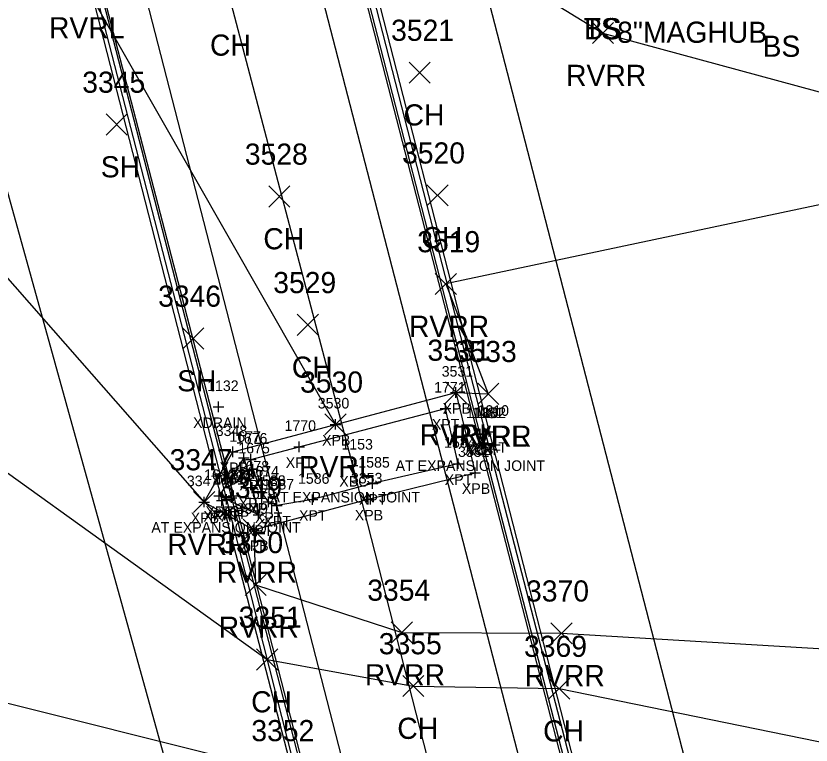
# Model space of a CAD drawing. Extents: x 1601151 to 1602912, y 499508 to 501770.
# Drawn here: x 1601542.5 to 1601617.7, y 500689.8 to 500758.7 of the extents above; entities that cross this region are included whole.
import ezdxf

# ---------------------------------------------------------------- set-up
doc = ezdxf.new("R2010")
doc.units = 0
for name, color, linetype in [('B_A', 7, 'Continuous'), ('B_C', 7, 'Continuous'), ('B_I', 7, 'Continuous'), ('B_TIC', 7, 'Continuous'), ('BB', 7, 'Continuous'), ('BDC', 7, 'Continuous'), ('BELB', 7, 'Continuous'), ('BF', 7, 'Continuous'), ('BR', 7, 'Continuous'), ('BSUBM', 7, 'Continuous'), ('C_C', 7, 'Continuous'), ('L_A', 7, 'Continuous'), ('L_I', 7, 'Continuous'), ('L_TIC', 7, 'Continuous'), ('LAWE', 7, 'Continuous'), ('LDEFAULT', 7, 'Continuous'), ('UCO', 7, 'Continuous')]:
    doc.layers.add(name, color=color, linetype=linetype)

msp = doc.modelspace()

# ---------------------------------------------------------------- linework, layer by layer
at = {"layer": 'B_TIC'}
for p, q in [((1601584.118, 500723.141), (1601584.193, 500723.141)), ((1601561.667, 500721.782), (1601561.743, 500721.782)), ((1601583.121, 500721.638), (1601583.197, 500721.638)), ((1601583.121, 500721.638), (1601583.197, 500721.638)), ((1601572.734, 500720.13), (1601572.81, 500720.13)), ((1601586.177, 500719.227), (1601586.253, 500719.227)), ((1601586.411, 500719.217), (1601586.487, 500719.217)), ((1601586.942, 500719.228), (1601587.018, 500719.228)), ((1601587.263, 500719.439), (1601587.339, 500719.439)), ((1601563.046, 500717.527), (1601563.122, 500717.527)), ((1601569.309, 500718.01), (1601569.385, 500718.01)), ((1601564.078, 500716.979), (1601564.154, 500716.979)), ((1601564.078, 500716.979), (1601564.154, 500716.979)), ((1601564.721, 500716.813), (1601564.797, 500716.813)), ((1601574.358, 500716.245), (1601574.434, 500716.245)), ((1601584.343, 500716.412), (1601584.419, 500716.412)), ((1601584.343, 500716.412), (1601584.419, 500716.412)), ((1601564.921, 500715.885), (1601564.997, 500715.885)), ((1601585.942, 500715.555), (1601586.018, 500715.555)), ((1601585.942, 500715.555), (1601586.018, 500715.555)), ((1601576.238, 500714.54), (1601576.314, 500714.54)), ((1601564.858, 500714.17), (1601564.934, 500714.17)), ((1601565.787, 500713.69), (1601565.863, 500713.69)), ((1601561.729, 500713.371), (1601561.805, 500713.371)), ((1601561.729, 500713.371), (1601561.805, 500713.371)), ((1601561.989, 500712.939), (1601562.065, 500712.939)), ((1601562.425, 500713.041), (1601562.501, 500713.041)), ((1601562.905, 500713.198), (1601562.981, 500713.198)), ((1601563.093, 500713.388), (1601563.169, 500713.388)), ((1601570.565, 500713.011), (1601570.641, 500713.011)), ((1601575.824, 500713.046), (1601575.899, 500713.046)), ((1601560.317, 500712.787), (1601560.393, 500712.787)), ((1601560.317, 500712.787), (1601560.393, 500712.787)), ((1601566.398, 500712.812), (1601566.474, 500712.812)), ((1601567.193, 500712.47), (1601567.269, 500712.47)), ((1601565.462, 500711.587), (1601565.538, 500711.587)), ((1601565.007, 500710.164), (1601565.082, 500710.164))]:
    msp.add_line(p, q, dxfattribs=at)
for points in [[(1601584.114, 500722.641), (1601584.114, 500723.641)], [(1601583.614, 500723.141), (1601584.614, 500723.141)], [(1601561.664, 500721.282), (1601561.664, 500722.282)], [(1601583.118, 500721.138), (1601583.118, 500722.138)], [(1601583.118, 500721.138), (1601583.118, 500722.138)], [(1601561.164, 500721.782), (1601562.164, 500721.782)], [(1601582.618, 500721.638), (1601583.618, 500721.638)], [(1601582.618, 500721.638), (1601583.618, 500721.638)], [(1601572.731, 500719.63), (1601572.731, 500720.63)], [(1601572.231, 500720.13), (1601573.231, 500720.13)], [(1601586.174, 500718.727), (1601586.174, 500719.727)], [(1601586.408, 500718.717), (1601586.408, 500719.717)], [(1601586.939, 500718.728), (1601586.939, 500719.728)], [(1601587.26, 500718.939), (1601587.26, 500719.939)], [(1601585.674, 500719.227), (1601586.674, 500719.227)], [(1601585.908, 500719.217), (1601586.908, 500719.217)], [(1601586.439, 500719.228), (1601587.439, 500719.228)], [(1601586.76, 500719.439), (1601587.76, 500719.439)], [(1601569.306, 500717.51), (1601569.306, 500718.51)], [(1601562.543, 500717.527), (1601563.543, 500717.527)], [(1601563.043, 500717.027), (1601563.043, 500718.027)], [(1601564.075, 500716.479), (1601564.075, 500717.479)], [(1601564.075, 500716.479), (1601564.075, 500717.479)], [(1601568.806, 500718.01), (1601569.806, 500718.01)], [(1601563.575, 500716.979), (1601564.575, 500716.979)], [(1601563.575, 500716.979), (1601564.575, 500716.979)], [(1601564.218, 500716.813), (1601565.218, 500716.813)], [(1601564.718, 500716.313), (1601564.718, 500717.313)], [(1601574.355, 500715.745), (1601574.355, 500716.745)], [(1601584.34, 500715.912), (1601584.34, 500716.912)], [(1601584.34, 500715.912), (1601584.34, 500716.912)], [(1601564.918, 500715.385), (1601564.918, 500716.385)], [(1601573.855, 500716.245), (1601574.855, 500716.245)], [(1601583.84, 500716.412), (1601584.84, 500716.412)], [(1601583.84, 500716.412), (1601584.84, 500716.412)], [(1601585.939, 500715.055), (1601585.939, 500716.055)], [(1601585.939, 500715.055), (1601585.939, 500716.055)], [(1601564.418, 500715.885), (1601565.418, 500715.885)], [(1601585.439, 500715.555), (1601586.439, 500715.555)], [(1601585.439, 500715.555), (1601586.439, 500715.555)], [(1601564.855, 500713.67), (1601564.855, 500714.67)], [(1601575.735, 500714.54), (1601576.735, 500714.54)], [(1601576.235, 500714.04), (1601576.235, 500715.04)], [(1601561.726, 500712.871), (1601561.726, 500713.871)], [(1601561.726, 500712.871), (1601561.726, 500713.871)], [(1601562.902, 500712.698), (1601562.902, 500713.698)], [(1601563.09, 500712.888), (1601563.09, 500713.888)], [(1601564.355, 500714.17), (1601565.355, 500714.17)], [(1601565.284, 500713.69), (1601566.284, 500713.69)], [(1601565.784, 500713.19), (1601565.784, 500714.19)], [(1601560.314, 500712.287), (1601560.314, 500713.287)], [(1601560.314, 500712.287), (1601560.314, 500713.287)], [(1601561.226, 500713.371), (1601562.226, 500713.371)], [(1601561.226, 500713.371), (1601562.226, 500713.371)], [(1601561.486, 500712.939), (1601562.486, 500712.939)], [(1601561.922, 500713.041), (1601562.922, 500713.041)], [(1601561.986, 500712.439), (1601561.986, 500713.439)], [(1601562.402, 500713.198), (1601563.402, 500713.198)], [(1601562.422, 500712.541), (1601562.422, 500713.541)], [(1601562.59, 500713.388), (1601563.59, 500713.388)], [(1601566.395, 500712.312), (1601566.395, 500713.312)], [(1601567.19, 500711.97), (1601567.19, 500712.97)], [(1601570.062, 500713.011), (1601571.062, 500713.011)], [(1601570.562, 500712.511), (1601570.562, 500713.511)], [(1601575.32, 500713.046), (1601576.32, 500713.046)], [(1601575.82, 500712.546), (1601575.82, 500713.546)], [(1601559.814, 500712.787), (1601560.814, 500712.787)], [(1601559.814, 500712.787), (1601560.814, 500712.787)], [(1601565.895, 500712.812), (1601566.895, 500712.812)], [(1601566.69, 500712.47), (1601567.69, 500712.47)], [(1601564.959, 500711.587), (1601565.959, 500711.587)], [(1601565.459, 500711.087), (1601565.459, 500712.087)], [(1601565.004, 500709.664), (1601565.004, 500710.664)], [(1601564.503, 500710.164), (1601565.504, 500710.164)]]:
    msp.add_lwpolyline(points, dxfattribs=at)
at = {"layer": 'BB'}
for points in [[(1601612.43, 500602.27), (1601552.33, 500834.638)], [(1601596.605, 500598.195), (1601536.682, 500830.877)]]:
    msp.add_lwpolyline(points, dxfattribs=at)
at = {"layer": 'BDC'}
for points in [[(1601626.62, 500562.484), (1601618.762, 500592.927), (1601608.069, 500634.25), (1601598.914, 500669.817), (1601586.174, 500719.227), (1601573.535, 500768.43), (1601563.157, 500808.618), (1601554.18, 500843.361), (1601545.696, 500876.636)], [(1601627.365, 500562.647), (1601626.817, 500562.743), (1601626.575, 500563.06), (1601618.94, 500592.981), (1601608.354, 500634.47), (1601599.142, 500669.932), (1601586.408, 500719.217), (1601573.699, 500768.593), (1601563.408, 500808.684), (1601554.3, 500843.382), (1601545.843, 500876.671)], [(1601521.711, 500869.959), (1601522.401, 500870.191), (1601530.668, 500838.288), (1601539.742, 500803.087), (1601549.8, 500763.941), (1601562.902, 500713.198), (1601575.298, 500665.088), (1601584.682, 500628.799), (1601595.241, 500588.098), (1601603.293, 500556.622), (1601602.827, 500556.326)], [(1601522.54, 500870.251), (1601530.887, 500838.161), (1601539.773, 500803.176), (1601550.059, 500763.65), (1601563.09, 500713.388), (1601575.504, 500665.097), (1601584.832, 500628.831), (1601595.285, 500588.334), (1601603.432, 500556.591), (1601602.763, 500556.075)]]:
    msp.add_lwpolyline(points, dxfattribs=at)
at = {"layer": 'BELB'}
msp.add_lwpolyline([(1601614.122, 500560.679), (1601606.109, 500592.04), (1601595.825, 500632.34), (1601585.652, 500672.123), (1601574.355, 500716.245), (1601561.498, 500765.241), (1601551.327, 500804.521), (1601542.34, 500839.856), (1601533.48, 500873.114)], dxfattribs=at)
at = {"layer": 'BF'}
for points in [[(1601546.596, 500876.467), (1601555.117, 500843.825), (1601564.25, 500808.582), (1601574.552, 500768.924), (1601587.26, 500719.439), (1601599.8, 500670.488), (1601609.07, 500634.571), (1601619.784, 500593.212)], [(1601521.711, 500869.959), (1601529.926, 500837.537), (1601538.825, 500802.891), (1601549.015, 500763.542), (1601561.986, 500712.939), (1601574.422, 500664.924), (1601583.827, 500628.557), (1601594.342, 500587.938), (1601602.827, 500556.326)]]:
    msp.add_lwpolyline(points, dxfattribs=at)
at = {"layer": 'BR'}
for points in [[(1601626.891, 500563.91), (1601619.486, 500592.933), (1601608.823, 500634.178), (1601599.631, 500670.204), (1601586.939, 500719.228), (1601574.289, 500768.594), (1601563.976, 500808.593), (1601554.991, 500843.345), (1601546.615, 500875.695)], [(1601521.915, 500869.371), (1601530.025, 500838.058), (1601539.084, 500802.864), (1601549.326, 500763.869), (1601562.422, 500713.041), (1601574.564, 500665.146), (1601584.098, 500628.637), (1601594.598, 500587.839), (1601602.424, 500557.542)]]:
    msp.add_lwpolyline(points, dxfattribs=at)
at = {"layer": 'BSUBM'}
for points in [[(1601560.314, 500712.787), (1601563.043, 500717.527), (1601572.731, 500720.13), (1601584.114, 500723.141), (1601585.939, 500715.555)], [(1601584.34, 500716.412), (1601576.235, 500714.54), (1601570.562, 500713.011), (1601567.19, 500712.47), (1601566.395, 500712.812), (1601565.784, 500713.69), (1601564.918, 500715.885), (1601564.718, 500716.813), (1601569.306, 500718.01), (1601583.118, 500721.638)], [(1601584.34, 500716.412), (1601583.118, 500721.638)], [(1601564.075, 500716.979), (1601564.855, 500714.17), (1601565.459, 500711.587), (1601561.726, 500713.371)], [(1601564.075, 500716.979), (1601561.726, 500713.371)], [(1601560.314, 500712.787), (1601565.004, 500710.164), (1601575.82, 500713.046), (1601585.939, 500715.555)]]:
    msp.add_lwpolyline(points, dxfattribs=at)
at = {"layer": 'L_TIC'}
for points in [[(1601597.015, 500756.122), (1601599.015, 500758.122)], [(1601599.015, 500756.122), (1601597.015, 500758.122)], [(1601579.679, 500752.388), (1601581.679, 500754.388)], [(1601581.679, 500752.388), (1601579.679, 500754.388)], [(1601551.055, 500747.481), (1601553.055, 500749.481)], [(1601553.055, 500747.481), (1601551.055, 500749.481)], [(1601566.423, 500740.68), (1601568.423, 500742.68)], [(1601568.423, 500740.68), (1601566.423, 500742.68)], [(1601581.368, 500740.788), (1601583.368, 500742.788)], [(1601583.368, 500740.788), (1601581.368, 500742.788)], [(1601582.161, 500732.402), (1601584.161, 500734.402)], [(1601584.161, 500732.402), (1601582.161, 500734.402)], [(1601569.117, 500728.536), (1601571.117, 500730.536)], [(1601571.117, 500728.536), (1601569.117, 500730.536)], [(1601558.278, 500727.253), (1601560.278, 500729.253)], [(1601560.278, 500727.253), (1601558.278, 500729.253)], [(1601583.114, 500722.141), (1601585.114, 500724.141)], [(1601585.114, 500722.141), (1601583.114, 500724.141)], [(1601586.174, 500722.02), (1601588.174, 500724.02)], [(1601588.174, 500722.02), (1601586.174, 500724.02)], [(1601586.174, 500722.02), (1601588.174, 500724.02)], [(1601588.174, 500722.02), (1601586.174, 500724.02)], [(1601571.731, 500719.13), (1601573.731, 500721.13)], [(1601573.731, 500719.13), (1601571.731, 500721.13)], [(1601559.314, 500711.787), (1601561.314, 500713.787)], [(1601561.314, 500711.787), (1601559.314, 500713.787)], [(1601564.004, 500709.164), (1601566.004, 500711.164)], [(1601566.004, 500709.164), (1601564.004, 500711.164)], [(1601564.184, 500703.956), (1601566.184, 500705.956)], [(1601566.184, 500703.956), (1601564.184, 500705.956)], [(1601577.995, 500699.455), (1601579.995, 500701.455)], [(1601579.995, 500699.455), (1601577.995, 500701.455)], [(1601593.089, 500699.378), (1601595.089, 500701.378)], [(1601595.089, 500699.378), (1601593.089, 500701.378)], [(1601565.274, 500696.902), (1601567.274, 500698.902)], [(1601567.274, 500696.902), (1601565.274, 500698.902)], [(1601579.087, 500694.394), (1601581.087, 500696.394)], [(1601581.087, 500694.394), (1601579.087, 500696.394)], [(1601592.867, 500694.148), (1601594.867, 500696.148)], [(1601594.867, 500694.148), (1601592.867, 500696.148)]]:
    msp.add_lwpolyline(points, dxfattribs=at)
at = {"layer": 'LAWE'}
for points in [[(1601318.619, 500789.616), (1601362.929, 500806.225), (1601394.458, 500804.484), (1601434.188, 500795.172), (1601527.957, 500788.908), (1601546.382, 500778.247), (1601558.004, 500777.295), (1601574.084, 500771.8), (1601598.015, 500757.122), (1601667.949, 500738.137), (1601705.277, 500715.12), (1601735.848, 500687.879), (1601768.331, 500671.256), (1601783.768, 500659.222)], [(1601521.092, 500757.434), (1601488.534, 500786.189), (1601547.387, 500770.546), (1601549.082, 500761.625), (1601572.731, 500720.13), (1601584.114, 500723.141), (1601587.174, 500723.02)], [(1601521.092, 500757.434), (1601560.314, 500712.787), (1601565.004, 500710.164), (1601565.184, 500704.956), (1601578.995, 500700.455), (1601594.089, 500700.378), (1601635.298, 500697.926), (1601669.086, 500704.243), (1601677.008, 500717.932), (1601649.987, 500725.338), (1601626.365, 500742.542), (1601583.161, 500733.402), (1601587.174, 500723.02)]]:
    msp.add_lwpolyline(points, dxfattribs=at)
at = {"layer": 'LDEFAULT'}
for points in [[(1601337.449, 500787.945), (1601362.968, 500800.687), (1601393.844, 500792.743), (1601431.563, 500786.236), (1601465.997, 500759.516), (1601526, 500726.821), (1601566.274, 500697.902), (1601580.087, 500695.394), (1601593.867, 500695.148), (1601641.186, 500685.491), (1601672.034, 500699.215), (1601695.981, 500708.013), (1601703.419, 500706.027), (1601734.398, 500680.193), (1601767.363, 500664.874), (1601779.678, 500657.306)], [(1601339.092, 500785.521), (1601337.449, 500787.945), (1601364.504, 500789.168), (1601390.07, 500781.719), (1601419.329, 500750.235), (1601457.253, 500747.586), (1601513.712, 500700.803), (1601568.037, 500687.176), (1601598.221, 500676.181), (1601647.03, 500668.884), (1601695.933, 500672.787), (1601756.552, 500665.637), (1601778.576, 500654.092)]]:
    msp.add_lwpolyline(points, dxfattribs=at)
at = {"layer": 'UCO'}
for points in [[(1601595.966, 500546.616), (1601489.931, 500928.889)], [(1601636.552, 500569.306), (1601558.395, 500871.752)]]:
    msp.add_lwpolyline(points, dxfattribs=at)

# ---------------------------------------------------------------- texts
at = {"layer": 'B_A'}
for s, p in [('XPB', (1601582.85, 500721.141)), ('XDRAIN', (1601559.274, 500719.782)), ('XPT', (1601581.838, 500719.638)), ('XPT', (1601581.838, 500719.638)), ('XPB', (1601571.467, 500718.13)), ('XCB', (1601584.91, 500717.227)), ('XCT', (1601585.128, 500717.217)), ('XFAT', (1601585.516, 500717.439)), ('XRF', (1601585.699, 500717.228)), ('XPT', (1601568.026, 500716.01)), ('XPB', (1601561.779, 500715.527)), ('XPT', (1601562.795, 500714.979)), ('XPT', (1601562.795, 500714.979)), ('XPT', (1601563.438, 500714.813)), ('XBC', (1601573.091, 500714.245)), ('XPT', (1601583.06, 500714.412)), ('XPT', (1601583.06, 500714.412)), ('XPT', (1601563.638, 500713.885)), ('XPB', (1601584.675, 500713.555)), ('XPB', (1601584.675, 500713.555)), ('XPT', (1601563.575, 500712.17)), ('XPT', (1601574.955, 500712.54)), ('XPT', (1601560.446, 500711.371)), ('XPT', (1601560.446, 500711.371)), ('XCT', (1601561.622, 500711.198)), ('XCB', (1601561.826, 500711.388)), ('XPT', (1601564.504, 500711.69)), ('XPB', (1601559.05, 500710.787)), ('XPB', (1601559.05, 500710.787)), ('XFAT', (1601560.242, 500710.939)), ('XRF', (1601561.182, 500711.041)), ('XPT', (1601565.115, 500710.812)), ('XPT', (1601565.91, 500710.47)), ('XPT', (1601569.282, 500711.011)), ('XPB', (1601574.556, 500711.046)), ('XPT', (1601564.179, 500709.587)), ('XPB', (1601563.74, 500708.164))]:
    msp.add_text(s, height=1, dxfattribs=at).set_placement(p)
at = {"layer": 'B_C'}
for p in [(1601578.414, 500715.727), (1601566.595, 500712.745), (1601555.33, 500709.888)]:
    msp.add_text('AT EXPANSION JOINT', height=1, dxfattribs=at).set_placement(p)
at = {"layer": 'B_I'}
for s, p in [('3531', (1601582.768, 500724.641)), ('1132', (1601560.601, 500723.282)), ('1771', (1601582.055, 500723.138)), ('1771', (1601582.055, 500723.138)), ('3530', (1601571.058, 500721.63)), ('1210', (1601586.154, 500720.939)), ('1180', (1601585.068, 500720.727)), ('1181', (1601585.629, 500720.717)), ('1182', (1601585.876, 500720.728)), ('1770', (1601567.916, 500719.51)), ('3348', (1601561.413, 500719.027)), ('1677', (1601562.705, 500718.479)), ('1677', (1601562.705, 500718.479)), ('1676', (1601563.32, 500718.313)), ('1584', (1601582.994, 500717.912)), ('1584', (1601582.994, 500717.912)), ('1675', (1601563.548, 500717.385)), ('1153', (1601573.292, 500717.745)), ('3532', (1601584.309, 500717.055)), ('3532', (1601584.309, 500717.055)), ('1678', (1601563.485, 500715.67)), ('1585', (1601574.889, 500716.04)), ('1133', (1601562.027, 500714.888)), ('1674', (1601564.414, 500715.19)), ('3347', (1601558.684, 500714.287)), ('3347', (1601558.684, 500714.287)), ('1680', (1601560.313, 500714.871)), ('1680', (1601560.313, 500714.871)), ('1161', (1601561.183, 500714.439)), ('1135', (1601561.359, 500714.541)), ('1134', (1601561.839, 500714.698)), ('1588', (1601565.049, 500714.312)), ('1586', (1601569.188, 500714.511)), ('3353', (1601574.19, 500714.546)), ('1587', (1601565.844, 500713.97)), ('1679', (1601564.085, 500713.087)), ('3349', (1601563.37, 500711.664))]:
    msp.add_text(s, height=1, dxfattribs=at).set_placement(p)
at = {"layer": 'C_C'}
msp.add_text('8"MAGHUB', height=2, dxfattribs=at).set_placement((1601599.352, 500756.203))
at = {"layer": 'L_A'}
for s, p in [('RVRL', (1601545.649, 500756.625)), ('TS', (1601596.187, 500756.537)), ('BS', (1601596.218, 500756.537)), ('CH', (1601560.871, 500754.987)), ('BS', (1601613.097, 500754.88)), ('RVRR', (1601594.527, 500752.122)), ('CH', (1601579.167, 500748.388)), ('SH', (1601550.543, 500743.481)), ('CH', (1601565.911, 500736.68)), ('CH', (1601580.856, 500736.788)), ('RVRR', (1601579.672, 500728.402)), ('CH', (1601568.605, 500724.536)), ('SH', (1601557.766, 500723.253)), ('RVRL', (1601580.681, 500718.141)), ('RVRR', (1601583.686, 500718.02)), ('RVRL', (1601583.741, 500718.02)), ('RVRL', (1601569.298, 500715.13)), ('RVRR', (1601556.826, 500707.787)), ('RVRR', (1601561.515, 500705.164)), ('RVRR', (1601561.695, 500699.956)), ('RVRR', (1601575.506, 500695.455)), ('RVRR', (1601590.601, 500695.378)), ('CH', (1601564.762, 500692.902)), ('CH', (1601578.575, 500690.394)), ('CH', (1601592.356, 500690.148))]:
    msp.add_text(s, height=2, dxfattribs=at).set_placement(p)
at = {"layer": 'L_I'}
for s, p in [('3521', (1601577.986, 500756.388)), ('3345', (1601548.795, 500751.481)), ('3520', (1601579.021, 500744.788)), ('3528', (1601564.163, 500744.68)), ('3519', (1601580.46, 500736.402)), ('3529', (1601566.849, 500732.536)), ('3346', (1601555.963, 500731.253)), ('3531', (1601581.421, 500726.141)), ('3533', (1601583.914, 500726.02)), ('3533', (1601583.914, 500726.02)), ('3530', (1601569.384, 500723.13)), ('3347', (1601557.054, 500715.787)), ('3349', (1601561.736, 500713.164)), ('3350', (1601561.837, 500707.956)), ('3354', (1601575.735, 500703.455)), ('3370', (1601590.743, 500703.378)), ('3351', (1601563.581, 500700.902)), ('3355', (1601576.827, 500698.394)), ('3369', (1601590.552, 500698.148)), ('3352', (1601564.778, 500690.176))]:
    msp.add_text(s, height=2, dxfattribs=at).set_placement(p)

doc.saveas('drawing.dxf')
